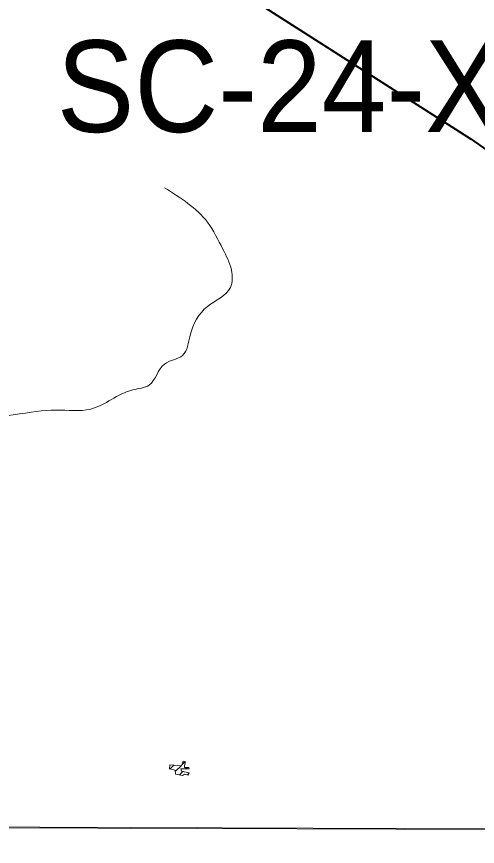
# Model space of a CAD drawing. Extents: x 553962 to 842807, y 8883888 to 9032388.
# Drawn here: x 598478 to 600994, y 8909822 to 8914352 of the extents above; entities that cross this region are included whole.
import ezdxf

# ---------------------------------------------------------------- set-up
doc = ezdxf.new("R2010")
doc.units = 0
doc.header["$LTSCALE"] = 150
doc.layers.add('6', color=7, linetype='Continuous', lineweight=13)

msp = doc.modelspace()

# ---------------------------------------------------------------- linework, layer by layer
at = {"layer": '6'}
for p, q in [((599315.9, 8910245.3), (599335.8, 8910265.2)), ((599343.8, 8910230.8), (599375.6, 8910262.5)), ((599379.9, 8910266.9), (599397.8, 8910284.7)), ((599367.8, 8910212.3), (599386.4, 8910230.9)), ((599400.9, 8910245.4), (599408.4, 8910253)), ((599410.3, 8910212.4), (599419.1, 8910221.2)), ((574653.9, 8910009.3), (626625.7, 8909822.1))]:
    msp.add_line(p, q, dxfattribs=at)
for points in [[(607600.8, 8920952.4), (596639.8, 8920989.8), (596608.8, 8909934.4), (607569.8, 8909894.9)], [(599378.7, 8910262.3), (599314.2, 8910266.7), (599311.8, 8910246.2), (599342.8, 8910239.1), (599345.6, 8910215.6), (599383.5, 8910210), (599394.2, 8910216.7), (599414.6, 8910211.2), (599420, 8910223.3), (599378.4, 8910232.8), (599374.7, 8910245.7), (599420.2, 8910245.3), (599418.8, 8910252.9), (599394.5, 8910253.1), (599393.8, 8910262.9), (599400.1, 8910284.1), (599388, 8910287.2), (599381, 8910270.6)]]:
    msp.add_lwpolyline(points, close=True, dxfattribs=at)
at = {"layer": '6', "lineweight": 40}
msp.add_lwpolyline([(599384.5, 8914691.3), (599431.6, 8914660.4), (600961.1, 8913682.3), (601460.1, 8913331.7), (601690.5, 8912983.4), (601771, 8912890.8), (601830.7, 8912847.9), (601883.5, 8912819.1), (601916.8, 8912809.3)], dxfattribs=at)
at = {"layer": '6'}
msp.add_spline([(596703.8, 8909915.9), (596714.2, 8910009.9), (596839.6, 8910140.6), (597012.1, 8910266), (597195, 8910391.4), (597330.8, 8910501.1), (597419.6, 8910610.8), (597498, 8910741.4), (597492.8, 8910882.5), (597613, 8910960.9), (597759.2, 8911034), (597905.6, 8911185.6), (597895.1, 8911300.5), (597968.2, 8911373.7), (597957.8, 8911425.9), (597853.3, 8911509.5), (597801.1, 8911598.3), (597889.9, 8911729), (598031, 8911870), (598140.7, 8911786.4), (598271.3, 8911875.3), (598354.9, 8911995.4), (598297.4, 8912120.8), (598459.4, 8912178.3), (598694.5, 8912204.4), (598882.6, 8912209.7), (599112.5, 8912314.2), (599201.4, 8912340.3), (599285, 8912455.2), (599384.2, 8912502.3), (599426, 8912612.4), (599520.1, 8912769.3), (599645.5, 8912873.8), (599650.7, 8912967.9), (599603.7, 8913082.9), (599520.1, 8913229.3), (599285, 8913417.5)], degree=3, dxfattribs=at)

# ---------------------------------------------------------------- texts
at = {"layer": '6', "width": 0.95}
msp.add_text('SC-24-X-D-I', height=500, dxfattribs=at).set_placement((598696.7, 8913722.1))

doc.saveas('drawing.dxf')
